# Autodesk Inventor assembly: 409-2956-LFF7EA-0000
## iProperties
Created: 2010-09
Part Number: 409-2956-LFF7EA-0000
Document SubType Name: Assembly
Designer: S. Boerckel
Mass: 2.80253e+06 g
Surface Area: 772426 cm^2
Volume: 373209 cm^3
Density: 7.50927 g/cm^3
Description: CONTROLS & ELECTRICAL
Material: ASSEMBLY
SMR: =<MATERIAL>
Author: S. Boerckel
Revision Number: 0
